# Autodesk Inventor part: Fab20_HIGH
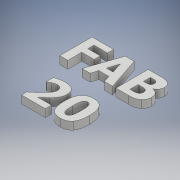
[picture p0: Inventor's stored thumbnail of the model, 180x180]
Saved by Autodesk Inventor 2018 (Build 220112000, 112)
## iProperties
Created: 2020-11
Part Number: Fab20_HIGH
Material: Genérico
Document SubType Name: Modeling
Designer: ULISES
Density: 1 g/cm^3
Appearance: Valor por defecto
Author: ULISES
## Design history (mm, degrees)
sketch "Boceto1"
  geometry: L1 (0, 0)-(60, 0); L2 (60, 0)-(60, 60); L3 (60, 60)-(0, 60); L4 (0, 60)-(0, 0); L5 (-0.169, 58.552)-(60, 58.552); L6 (60, 58.552)-(60, 0); L7 (60, 0)-(-0.169, 0); L8 (-0.169, 0)-(-0.169, 58.552)
  constraints: 8 end point, 2 parallel, 1 coincident, 1 horizontal, 1 perpendicular, 2 other
  dimensions: "d0" = 60 distance of L3.end L1.start; "d1" = 60 distance of L2.end L3.end
extrude "Extrusión1" new body sketch "Boceto1" distance "d2" = 4.8; taper "d3" = 0 deg
node "Sólido1"
